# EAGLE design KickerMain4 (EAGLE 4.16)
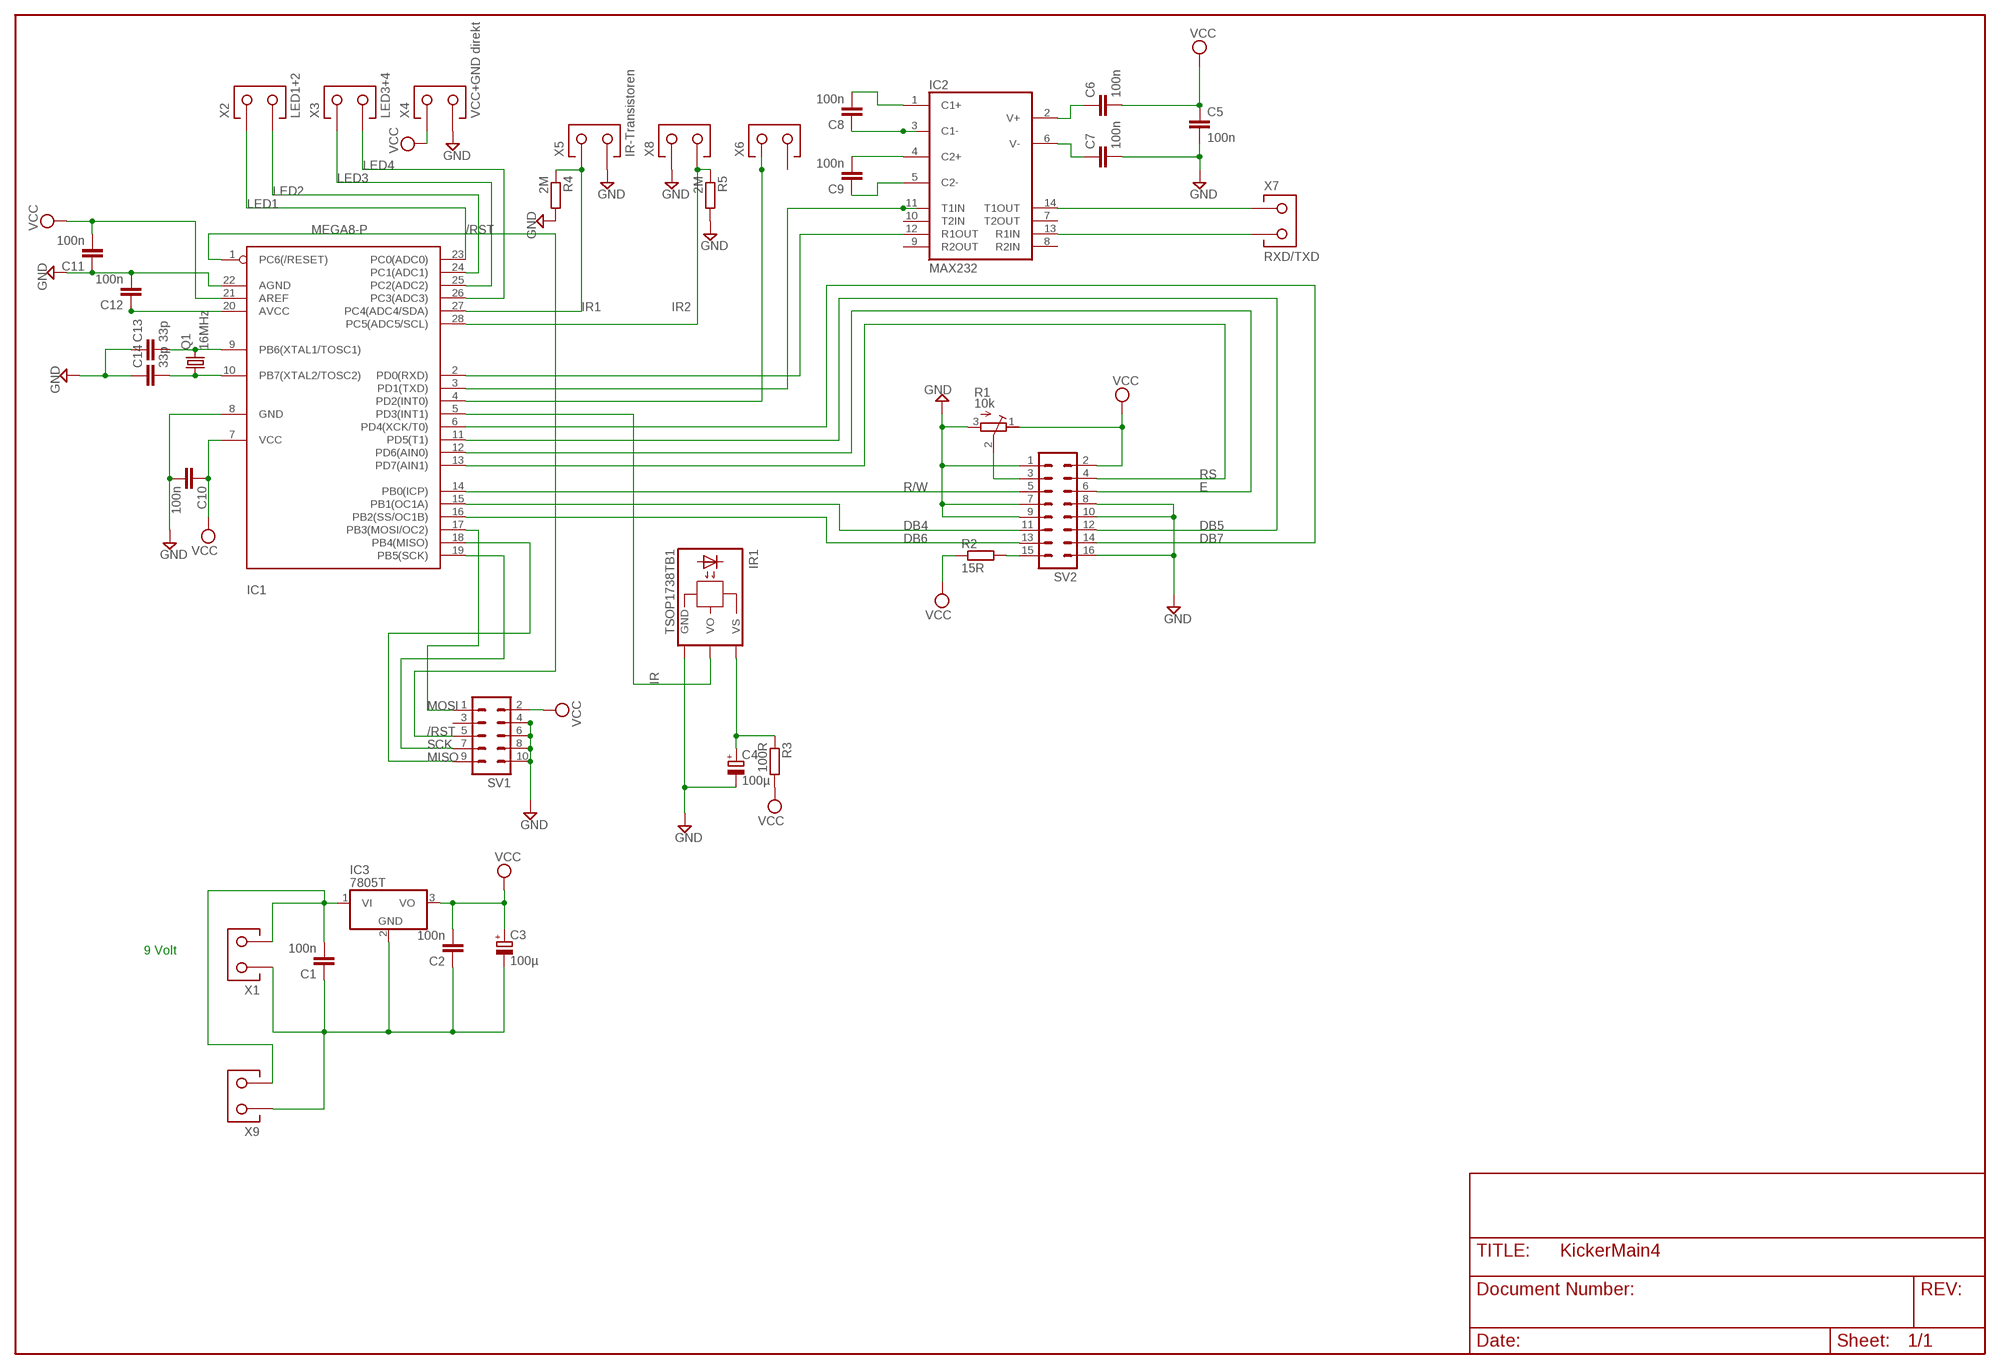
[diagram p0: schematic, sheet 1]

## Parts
C1  100n  C-EU025-025X050  [C025-025X050]
C2  100n  C-EU025-025X050  [C025-025X050]
C3  100µ  CPOL-EUE2.5-6  [E2,5-6]
C4  100µ  CPOL-EUE2.5-6  [E2,5-6]
C5  100n  C-EU025-025X050  [C025-025X050]
C6  100n  C-EU025-025X050  [C025-025X050]
C7  100n  C-EU025-025X050  [C025-025X050]
C8  100n  C-EU025-025X050  [C025-025X050]
C9  100n  C-EU025-025X050  [C025-025X050]
C10  100n  C-EU025-025X050  [C025-025X050]
C11  100n  C-EU025-025X050  [C025-025X050]
C12  100n  C-EU025-025X050  [C025-025X050]
C13  33p  C-EUC1206K  [C1206K]
C14  33p  C-EUC1206K  [C1206K]
IC1  MEGA8-P  [DIL28-3]
IC2  MAX232  [DIL16]
IC3  7805T  [TO220H]
IR1  TSOP1738TB1  [TSOP17_TB1]
Q1  16MHz  CRYTALHC49U-V  [HC49U-V]
R1  10k  R-TRIMMT93YB  [RTRIMT93YB]
R2  15R  R-EU_0207/10  [0207/10]
R3  100R  R-EU_0207/10  [0207/10]
R4  2M  R-EU_0207/10  [0207/10]
R5  2M  R-EU_0207/10  [0207/10]
SV1  ML10  [ML10]
SV2  ML16  [ML16]
X1  AKL-2_3,5  [AKL-2_3,5]
X2  LED1+2  AKL-2_3,5  [AKL-2_3,5]
X3  LED3+4  AKL-2_3,5  [AKL-2_3,5]
X4  VCC+GND direkt  AKL-2_3,5  [AKL-2_3,5]
X5  IR-Transistoren  AKL-2_3,5  [AKL-2_3,5]
X6  AKL-2_3,5  [AKL-2_3,5]
X7  RXD/TXD  AKL-2_3,5  [AKL-2_3,5]
X8  AKL-2_3,5  [AKL-2_3,5]
X9  AKL-2_3,5  [AKL-2_3,5]

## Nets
+9V: C1.2 IC3.1(VI) X1.P$2 X9.P$2
/RST: IC1.1(PC6(/RESET)) SV1.5
AVCC: C12.1 IC1.20(AVCC)
DB4: IC1.15(PB1(OC1A)) SV2.11
DB5: IC1.11(PD5(T1)) SV2.12
DB6: IC1.16(PB2(SS/OC1B)) SV2.13
DB7: IC1.6(PD4(XCK/T0)) SV2.14
E: IC1.12(PD6(AIN0)) SV2.6
GND: C4.- C5.2 C7.2 C10.2 C11.1 C12.2 C13.1 C14.1 IC1.8(GND) IC1.22(AGND) IR1.GND R1.3(E) R4.2 R5.2 SV1.4 SV1.6 SV1.8 SV1.10 SV2.1 SV2.7 SV2.8 SV2.9 SV2.10 SV2.16 X4.P$2 X5.P$2 X8.P$1
GND9V: C1.1 C2.1 C3.- IC3.2(GND) X1.P$1 X9.P$1
IO: IC1.4(PD2(INT0)) X6.P$1
IR: IC1.5(PD3(INT1)) IR1.VO
IR1: IC1.27(PC4(ADC4/SDA)) R4.1 X5.P$1
IR2: IC1.28(PC5(ADC5/SCL)) R5.1 X8.P$2
LED1: IC1.23(PC0(ADC0)) X2.P$1
LED2: IC1.24(PC1(ADC1)) X2.P$2
LED3: IC1.25(PC2(ADC2)) X3.P$1
LED4: IC1.26(PC3(ADC3)) X3.P$2
MISO: IC1.18(PB4(MISO)) SV1.9
MOSI: IC1.17(PB3(MOSI/OC2)) SV1.1
N$2: R2.2 SV2.15
N$4: R1.2(S) SV2.3
N$6: C8.1 IC2.3(C1-)
N$7: C8.2 IC2.1(C1+)
N$8: C9.2 IC2.4(C2+)
N$9: C9.1 IC2.5(C2-)
N$10: C6.1 IC2.2(V+)
N$11: C7.1 IC2.6(V-)
N$14: IC1.2(PD0(RXD)) IC2.12(R1OUT)
N$18: C4.+ IR1.VS R3.1
N$24: IC1.3(PD1(TXD)) IC2.11(T1IN)
PCP2: IC2.14(T1OUT) X7.P$1
PCP3: IC2.13(R1IN) X7.P$2
R/W: IC1.14(PB0(ICP)) SV2.5
RS: IC1.13(PD7(AIN1)) SV2.4
SCK: IC1.19(PB5(SCK)) SV1.7
VCC: C2.2 C3.+ C5.1 C6.2 C10.1 C11.2 IC1.7(VCC) IC1.21(AREF) IC3.3(VO) R1.1(A) R2.1 R3.2 SV1.2 SV2.2 X4.P$1
XTAL1: C13.2 IC1.9(PB6(XTAL1/TOSC1)) Q1.2
XTAL2: C14.2 IC1.10(PB7(XTAL2/TOSC2)) Q1.1
Unconnected: IC2.7(T2OUT) IC2.8(R2IN) IC2.9(R2OUT) IC2.10(T2IN) SV1.3 X6.P$2

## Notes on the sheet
- 9 Volt

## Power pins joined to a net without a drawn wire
GND: IC2.15(GND)
VCC: IC2.16(VCC)

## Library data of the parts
C1 C2 C5-C14 = rcl:C-EU: CAPACITOR, European symbol
C3 C4 = rcl:CPOL-EU: POLARIZED CAPACITOR, European symbol
IC1 = atmel:MEGA8-P: MICROCONTROLLER 8 Kbytes FLASH 1 kbytes SRAM 512 bytes EEPROM USART 4-channel 10 bit ADC 2-channel 8 bit ADC Source: avr.lbr
IC2 = maxim:MAX232: RS232 TRANSEIVER
IC3 = linear:78*: Positive VOLTAGE REGULATOR
IR1 = telefunken:TSOP17*TB1: TSOP17..TB1 IR Receiver Modules for Remote Control Systems Source: http://www.vishay.com/docs/82042/82042.pdf
Q1 = crystal:CRYTAL: CRYSTAL
R1 = rcl:R-TRIMM: Trimm resistor
R2-R5 = rcl:R-EU_: RESISTOR, European symbol
SV1 = con-harting-ml:ML10: HARTING
SV2 = con-harting-ml:ML16: HARTING
X1-X9 = 0mylib:AKL-2_3,5

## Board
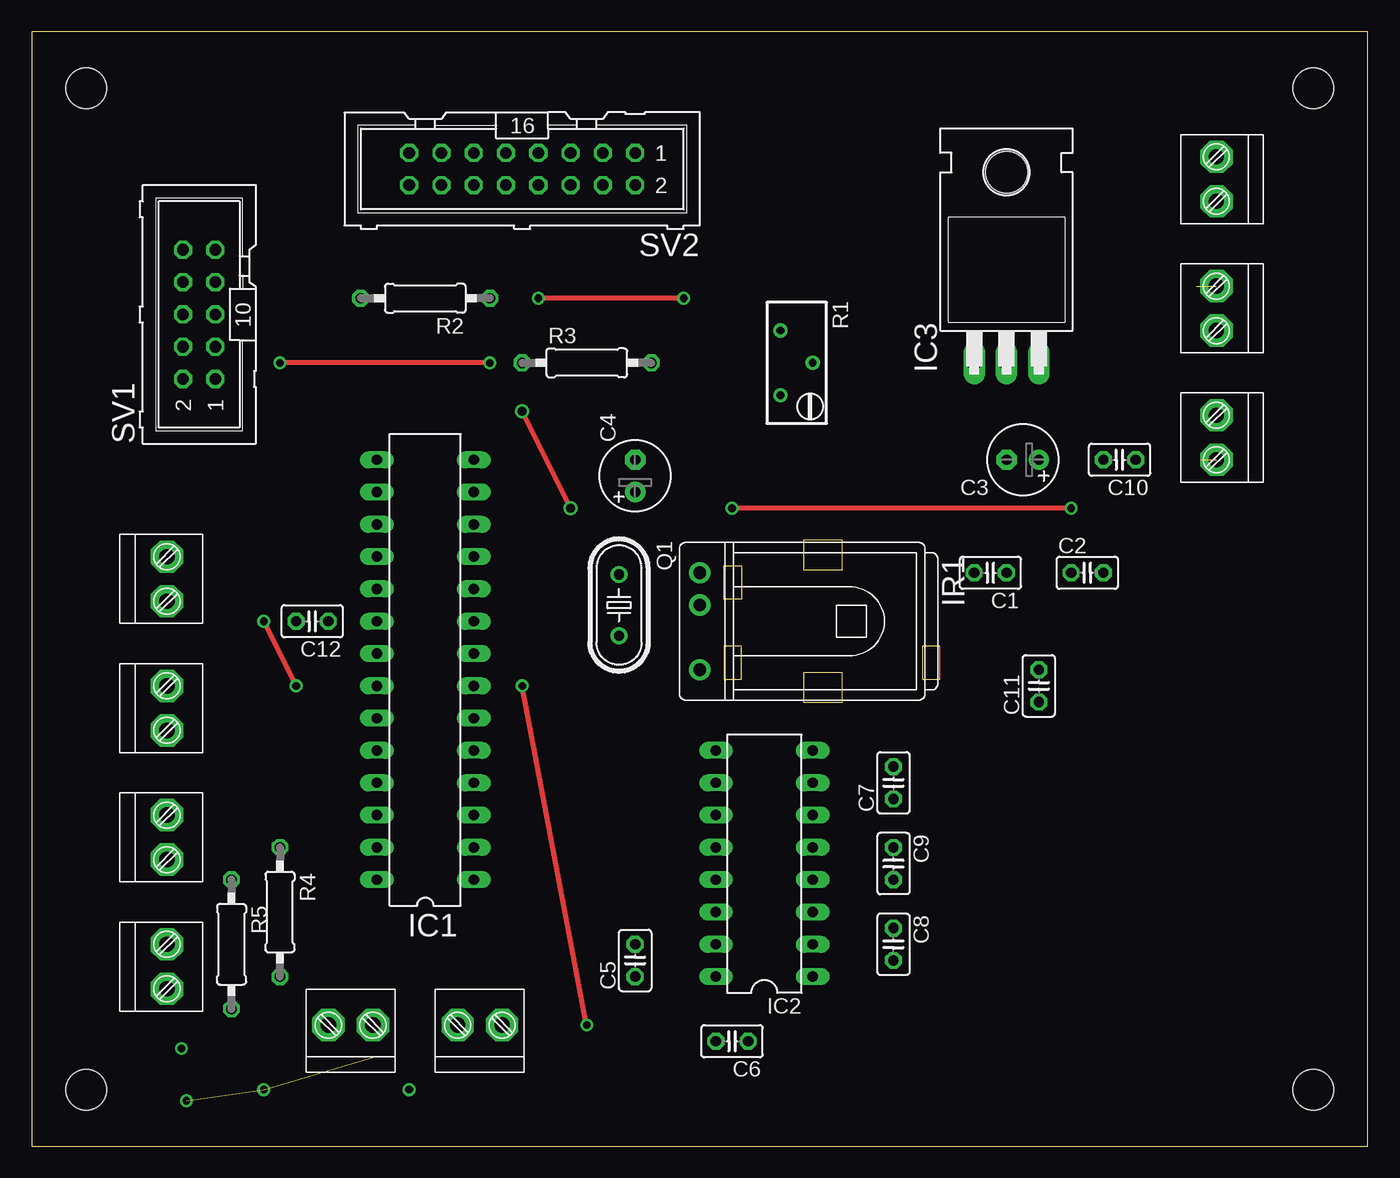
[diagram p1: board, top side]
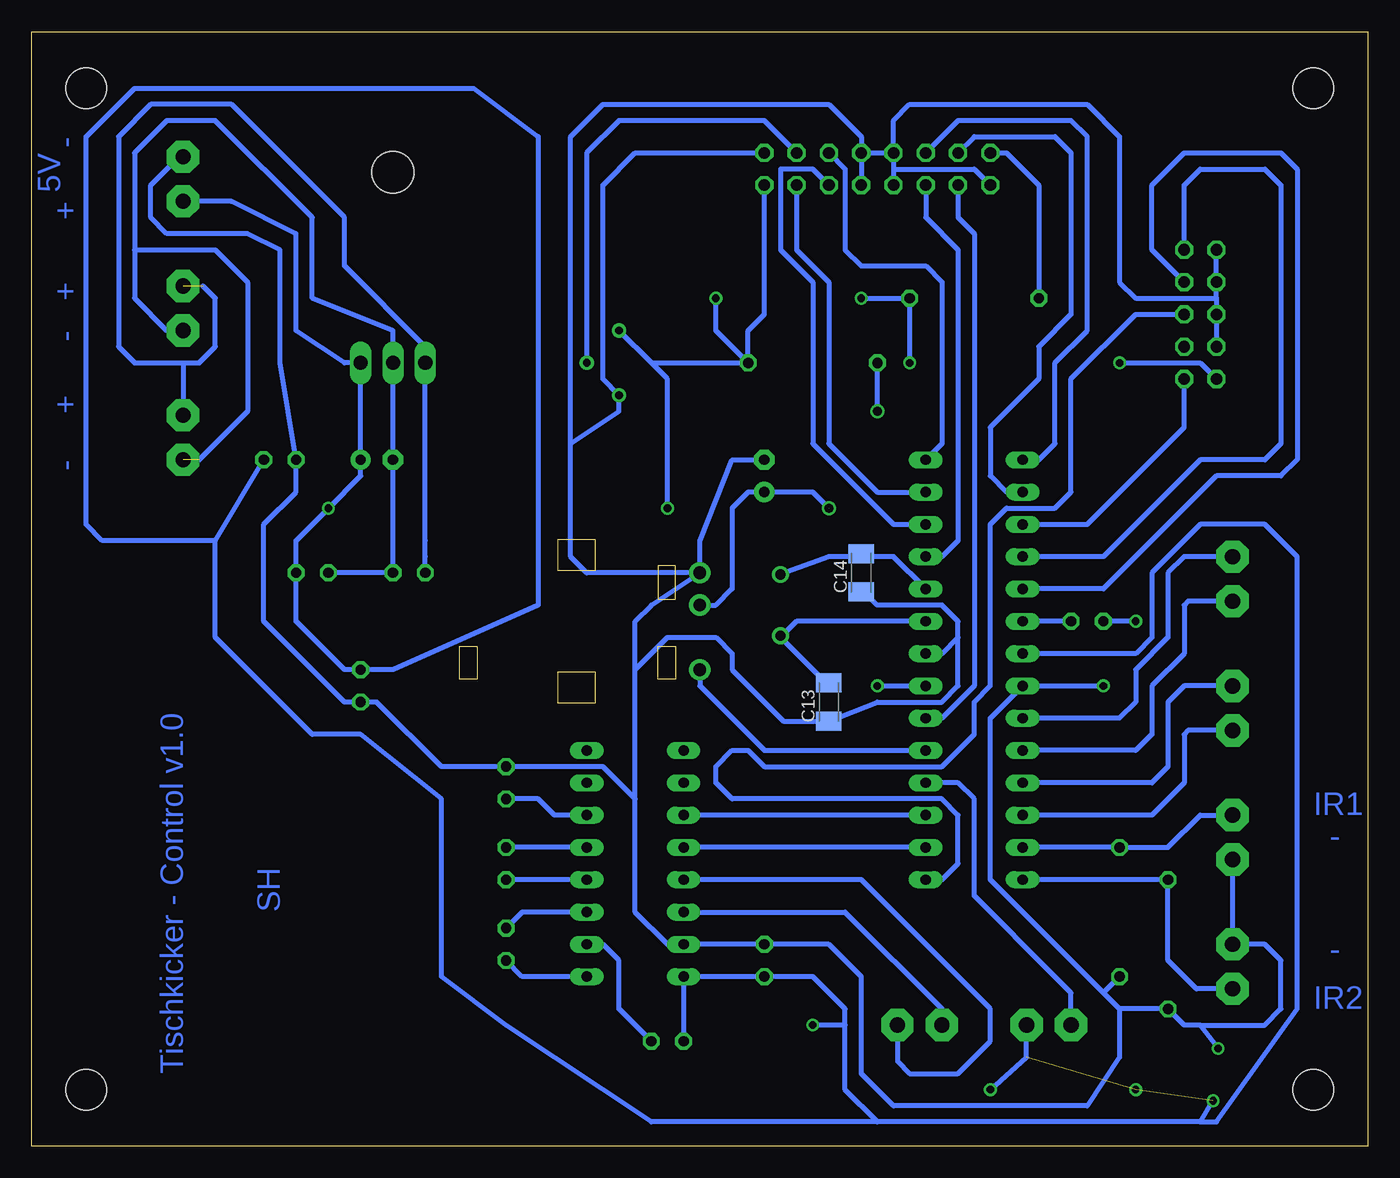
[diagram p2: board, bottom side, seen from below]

Size 105.08 x 87.62 mm. Coordinates in mm from the lower left corner, seen from the top.
Outline: 0,0 105.08,0 105.08,87.62 0,87.62 0,0
Copper layers (1*16): Top 0.035mm / dielectric 1.5mm / Bottom 0.035mm
Design rules "default": minimum track width 10mil, minimum drill 24mil, track to track 8mil, track to pad 8mil, pad to pad 8mil, via to via 8mil, smd to smd 8mil, copper to edge 40mil, drill to drill 8mil, minimum pad ring 10mil, minimum via ring 8mil, stop-mask expansion 4mil, vias tented up to drill 0mil, thermal gap 10mil
Holes 3.2 mm at 4.28,83.18 4.28,4.44 100.8,83.18 100.8,4.44

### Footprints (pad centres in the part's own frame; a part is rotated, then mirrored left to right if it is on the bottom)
C025-025X050 = drill 0.813 octagon: 1 -1.27,0; 2 1.27,0
E2,5-6 = drill 0.813 pad 1.6 round: + -1.27,0 | drill 0.813 pad 1.6 octagon: - 1.27,0
C1206K = smd 1.5 x 2: 1 -1.5,0; 2 1.5,0
DIL28-3 = drill 0.813 long: 1 -16.51,-3.81; 2 -13.97,-3.81; 3 -11.43,-3.81; 4 -8.89,-3.81; 5 -6.35,-3.81; 6 -3.81,-3.81; 7 -1.27,-3.81; 8 1.27,-3.81; 9 3.81,-3.81; 10 6.35,-3.81; 11 8.89,-3.81; 12 11.43,-3.81; 13 13.97,-3.81; 14 16.51,-3.81; 15 16.51,3.81; 16 13.97,3.81; 17 11.43,3.81; 18 8.89,3.81; 19 6.35,3.81; 20 3.81,3.81; 21 1.27,3.81; 22 -1.27,3.81; 23 -3.81,3.81; 24 -6.35,3.81; 25 -8.89,3.81; 26 -11.43,3.81; 27 -13.97,3.81; 28 -16.51,3.81
DIL16 = drill 0.813 long: 1 -8.89,-3.81; 2 -6.35,-3.81; 3 -3.81,-3.81; 4 -1.27,-3.81; 5 1.27,-3.81; 6 3.81,-3.81; 7 6.35,-3.81; 8 8.89,-3.81; 9 8.89,3.81; 10 6.35,3.81; 11 3.81,3.81; 12 1.27,3.81; 13 -1.27,3.81; 14 -3.81,3.81; 15 -6.35,3.81; 16 -8.89,3.81
TO220H = drill 1.118 long: 1 -2.54,-10.16; 2 0,-10.16; 3 2.54,-10.16 | hole 3.302: 0,4.826
TSOP17_TB1 = drill 1 pad 1.676 round: GND 0,-3.81; VO 0,3.81; VS 0,-1.27
HC49U-V = drill 0.813 round: 1 -2.413,0; 2 2.413,0
RTRIMT93YB = drill 0.61 round: 1 1.27,-2.54; 2 -1.27,0; 3 1.27,2.54
0207/10 = drill 0.813 octagon: 1 -5.08,0; 2 5.08,0
ML10 = drill 0.914 octagon: 1 -5.08,-1.27; 2 -5.08,1.27; 3 -2.54,-1.27; 4 -2.54,1.27; 5 0,-1.27; 6 0,1.27; 7 2.54,-1.27; 8 2.54,1.27; 9 5.08,-1.27; 10 5.08,1.27
ML16 = drill 0.914 octagon: 1 -8.89,-1.27; 2 -8.89,1.27; 3 -6.35,-1.27; 4 -6.35,1.27; 5 -3.81,-1.27; 6 -3.81,1.27; 7 -1.27,-1.27; 8 -1.27,1.27; 9 1.27,-1.27; 10 1.27,1.27; 11 3.81,-1.27; 12 3.81,1.27; 13 6.35,-1.27; 14 6.35,1.27; 15 8.89,-1.27; 16 8.89,1.27
AKL-2_3,5 = drill 1.2 pad 2.54 octagon: P$1 0,0; P$2 3.5,0

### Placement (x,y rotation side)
C1  75.4,45.08 180 top
C2  83.02,45.08 0 top
C3  77.94,53.97 180 top
C4  47.46,52.7 90 top
C5  47.46,14.6 90 top
C6  55.08,8.25 180 top
C7  67.78,28.57 90 top
C8  67.78,15.87 270 top
C9  67.78,22.22 270 top
C10  85.56,53.97 180 top
C11  79.21,36.19 90 top
C12  22.06,41.27 180 top
C13  42.38,34.92 90 bottom
C14  39.84,45.08 90 bottom
IC1  30.95,37.46 90 top
IC2  57.62,22.22 90 top
IC3  76.67,71.75 0 top
IR1  52.54,41.27 180 top
Q1  46.19,42.54 270 top
R1  60.16,61.59 180 top
R2  30.95,66.67 180 top
R3  43.65,61.59 0 top
R4  19.52,18.41 270 top
R5  15.71,15.87 270 top
SV1  13.17,65.4 90 top
SV2  38.57,76.83 180 top
X1  93.18,64.13 90 top
X2  10.63,46.35 270 top
X3  10.63,36.19 270 top
X4  93.18,74.29 90 top
X5  10.63,26.03 270 top
X6  23.33,9.52 0 top
X7  33.49,9.52 0 top
X8  10.63,15.87 270 top
X9  93.18,53.97 90 top

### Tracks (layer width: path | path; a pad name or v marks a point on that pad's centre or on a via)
+9V  (1 unrouted)
  Bottom 0.406: 74.13,46.35 IC3.1 74.13,62.86 80.48,69.21 80.48,73.02 89.37,81.91 95.72,81.91 98.26,79.37 98.26,62.86 96.99,61.59 93.18,61.59 | 91.6,67.63 90.64,66.67 90.64,62.86 91.91,61.59 93.18,61.59 | C1.2 74.13,46.35 | 74.13,46.35 74.13,47.62 | 93.18,61.59 X9.P$2
/RST
  Bottom 0.406: IC1.1 33.49,20.95 32.22,22.22 32.22,26.03 33.49,27.3 50,27.3 51.27,28.57 51.27,29.84 50,31.11 48.73,31.11 47.46,29.84 33.49,29.84 30.95,32.38 30.95,34.92 29.68,36.19 29.68,48.89 28.41,50.16 24.6,50.16 23.33,51.43 23.33,60.32 18.25,65.4 SV1.5
AVCC
  Bottom 0.406: C12.1 IC1.20
DB4
  Bottom 0.406: IC1.15 25.87,53.97 24.6,55.24 24.6,61.59 22.06,64.13 22.06,79.37 23.33,80.64 32.22,80.64 SV2.11
DB5
  Bottom 0.406: SV2.12 34.76,73.02 32.22,70.48 32.22,47.62 33.49,46.35 IC1.11
DB6
  Bottom 0.406: SV2.13 30.95,79.37 24.6,79.37 23.33,78.1 23.33,65.4 25.87,62.86 25.87,60.32 29.68,56.51 29.68,52.7 28.41,51.43 IC1.16
DB7
  Bottom 0.406: SV2.14 32.22,73.02 30.95,71.75 30.95,36.19 33.49,33.65 IC1.6
E
  Bottom 0.406: SV2.6 43.65,76.83 46.19,76.83 46.19,70.48 43.65,67.94 43.65,55.24 37.3,48.89 IC1.12
GND  (via drill 0.6)
  Top 0.406: v20.79,36.19 v18.25,41.27
  Bottom 0.406: 37.3,76.83 SV2.10 | SV2.9 37.3,76.83 | SV2.7 SV2.8 | SV2.16 30.95,76.83 37.3,76.83 | SV2.9 37.3,80.64 36.03,81.91 22.06,81.91 19.52,79.37 19.52,67.94 18.25,66.67 11.9,66.67 | 11.9,66.67 SV1.8 SV1.10 | 11.9,66.67 SV1.6 SV1.4 | SV2.7 SV2.9 | 57.62,27.3 57.62,18.41 55.08,15.87 IC2.15 C5.2 42.38,15.87 39.84,13.33 39.84,5.71 37.3,3.17 22.06,3.17 19.52,6.98 19.52,10.79 | C13.1 38.57,34.92 33.49,34.92 32.22,36.19 32.22,40 | 32.22,40 32.22,41.27 33.49,42.54 38.57,42.54 39.84,43.81 C14.1 | SV2.1 57.62,78.1 60.16,75.56 60.16,60.32 R1.3 58.89,57.78 62.7,55.24 | X4.P$2 93.49,77.79 95.72,75.56 95.72,73.02 94.45,71.75 88.1,71.75 85.56,70.48 85.56,61.59 C10.2 84.29,51.43 86.83,48.89 86.83,41.27 80.48,34.92 C11.1 77.94,34.92 72.86,29.84 C7.2 60.16,29.84 57.62,27.3 | 62.7,55.24 62.7,46.35 61.43,45.08 IR1.GND | SV2.7 39.84,79.37 42.38,81.91 60.16,81.91 62.7,79.37 62.7,55.24 | C4.- 50,53.97 52.54,47.62 IR1.GND | IR1.GND 56.35,42.54 57.62,41.27 57.62,37.46 | 57.62,27.3 57.62,37.46 | v18.25,41.27 C12.2 | v20.79,36.19 IC1.22 29.68,33.65 29.68,20.95 20.79,12.06 | 19.52,10.79 20.79,12.06 | 20.79,12.06 R4.2 | X5.P$2 X8.P$1 8.09,15.87 6.82,14.6 6.82,10.79 8.09,9.52 13.17,9.52 | 19.52,10.79 R5.2 14.44,9.52 13.17,9.52 | v11.77,7.68 13.17,9.52 | C13.1 42.38,33.65 | C13.1 45.96,33.42 50,37.46 50,38.73 51.27,40 55.08,40 57.62,37.46 | IC1.8 33.49,38.73 32.22,40
GND9V  (1 unrouted)
  Bottom 0.406: X1.P$1 94.45,64.13 96.99,66.67 96.99,70.48 | 96.99,70.48 96.99,78.1 94.45,80.64 90.64,80.64 83.02,73.02 83.02,66.67 76.67,64.13 IC3.2 C3.- C1.1 C2.1 | 91.91,53.97 88.1,57.78 88.1,67.94 90.64,70.48 96.99,70.48
IO
  Bottom 0.406: IC1.4 32.22,28.57 30.95,27.3 30.95,19.68 24.6,13.33 | 24.6,13.33 24.29,13.02 | X6.P$1 23.33,12.06 24.6,13.33
IR
  Bottom 0.406: IR1.VO 52.54,36.19 47.46,31.11 IC1.5
IR1
  Bottom 0.406: IC1.27 R4.1 15.71,23.49 13.17,26.03 X5.P$1
IR2
  Bottom 0.406: X8.P$2 13.48,12.37 15.71,14.6 R5.1 IC1.28
LED1
  Bottom 0.406: X2.P$1 14.44,46.35 15.71,45.08 15.71,40 18.25,37.46 18.25,34.92 19.52,33.65 IC1.23
LED2
  Bottom 0.406: X2.P$2 14.13,42.85 14.44,42.54 14.44,38.73 16.98,36.19 16.98,32.38 18.25,31.11 IC1.24
LED3
  Bottom 0.406: X3.P$1 14.44,36.19 15.71,34.92 15.71,29.84 16.98,28.57 IC1.25
LED4
  Bottom 0.406: X3.P$2 14.13,32.69 14.44,32.38 14.44,28.57 16.98,26.03 IC1.26
MISO
  Bottom 0.406: SV1.9 14.44,75.56 13.17,76.83 8.09,76.83 6.82,75.56 6.82,55.24 8.09,53.97 13.17,53.97 20.79,46.35 IC1.18
MOSI
  Bottom 0.406: SV1.1 14.44,56.51 22.06,48.89 IC1.17
N$1  (via drill 0.7)
  other vias: 42.38,50.16
N$2
  Bottom 0.406: SV2.15 28.41,78.1 25.87,75.56 R2.2
N$3  (via drill 0.7)
  other vias: 38.57,57.78
N$4
  Bottom 0.406: SV2.3 47.46,80.64 58.89,80.64 61.43,78.1 R1.2
N$5  (via drill 0.6)
  other vias: 39.84,66.67
N$6
  Bottom 0.406: IC2.3 66.51,18.41 C8.1
N$7
  Bottom 0.406: IC2.1 66.51,13.33 C8.2
N$8
  Bottom 0.406: IC2.4 C9.2
N$9
  Bottom 0.406: IC2.5 C9.1
N$10
  Bottom 0.406: C6.1 58.89,10.79 58.89,14.6 60.16,15.87 IC2.2
N$11
  Bottom 0.406: IC2.6 63.97,26.03 65.24,27.3 C7.1
N$13  (via drill 0.6)
  other vias: 51.27,66.67
N$14
  Bottom 0.406: IC1.2 IC2.12
N$15  (via drill 0.6)
  other vias: 19.52,61.59
N$16  (via drill 0.6)
  other vias: 36.03,61.59
N$17  (via drill 0.6)
  other vias: 18.25,41.27
N$18  (via drill 0.7)  (1 unrouted)
  Top 0.406: 42.38,50.16 v38.57,57.78
  Bottom 0.406: 42.38,50.16 43.65,51.43 C4.+ 48.73,51.43 50,50.16 50,43.81 51.27,42.54 IR1.VS | v38.57,57.78 R3.1
N$20  (via drill 0.6)
  other vias: 43.65,9.52
N$21  (via drill 0.6)
  other vias: 38.57,36.19
N$22  (via drill 0.6)
  other vias: 81.75,50.16
N$23  (via drill 0.6)
  other vias: 55.08,50.16
N$24
  Bottom 0.406: IC1.3 IC2.11
PCP2
  Bottom 0.406: IC2.14 41.11,18.41 33.49,10.79 X7.P$1
PCP3
  Bottom 0.406: X7.P$2 36.99,6.67 36.03,5.71 32.22,5.71 29.68,8.25 29.68,10.79 39.84,20.95 IC2.13
R/W
  Bottom 0.406: SV2.5 41.11,76.83 41.11,70.48 39.84,69.21 34.76,69.21 33.49,67.94 33.49,55.24 IC1.14
RS
  Bottom 0.406: SV2.4 44.92,70.48 42.38,67.94 42.38,55.24 38.57,51.43 IC1.13
SCK
  Bottom 0.406: SV1.7 16.98,70.48 16.98,75.56 14.44,78.1 6.82,78.1 5.55,76.83 5.55,53.97 6.82,52.7 11.9,52.7 20.79,43.81 IC1.19
VCC  (via drill 0.6)  (2 unrouted)
  Top 0.406: v51.27,66.67 v39.84,66.67 | v36.03,61.59 v19.52,61.59 | v43.65,9.52 v38.57,36.19 | v81.75,50.16 v55.08,50.16
  Bottom 0.406: 26.84,9.52 26.84,6.98 v29.68,4.44 | C6.2 IC2.16 C5.1 43.65,13.33 41.11,10.79 41.11,9.52 | IC1.21 18.25,38.73 16.98,40 16.98,45.08 13.17,48.89 8.09,48.89 5.55,46.35 5.55,10.79 11.9,1.9 13.17,1.9 | 41.11,9.52 41.11,4.44 38.57,1.9 | SV2.2 47.46,65.4 48.73,64.13 R3.2 | 56.35,61.59 R3.2 | X4.P$1 89.37,74.29 84.29,71.75 84.29,64.13 80.48,61.59 IC3.3 C3.+ 79.21,52.7 v81.75,50.16 84.29,47.62 C2.2 84.29,41.27 80.48,37.46 C11.2 76.67,37.46 65.24,42.54 65.24,79.37 70.32,83.18 96.99,83.18 100.8,79.37 100.8,48.89 99.53,47.62 90.64,47.62 | v39.84,66.67 R2.1 v36.03,61.59 | v51.27,66.67 51.27,64.13 R3.2 | SV1.2 13.17,61.59 v19.52,61.59 | v38.57,36.19 IC1.7 | 41.11,9.52 v43.65,9.52 | 56.35,61.59 R1.1 | 56.35,61.59 55.08,60.32 v55.08,50.16 | 13.17,1.9 38.57,1.9 | 38.57,1.9 56.35,1.9 67.78,9.52 72.86,13.33 72.86,27.3 79.21,32.38 83.02,32.38 90.64,40 90.64,47.62 | 90.64,47.62 C10.1 | 13.17,1.9 v12.17,3.57
  other vias: 18.25,4.44
XTAL1
  Bottom 0.406: C13.2 42.38,36.19 46.19,40 | 46.19,40 Q1.2 | IC1.9 44.92,41.27 46.19,40
XTAL2
  Bottom 0.406: Q1.1 42.38,46.35 39.84,46.35 | IC1.10 37.3,46.35 39.84,46.35 | 39.84,46.35 C14.2

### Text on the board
Bottom: - | 5V | + | + | - | + | - | IR1 | - | SH | - | IR2 | Tischkicker - Control v1.0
